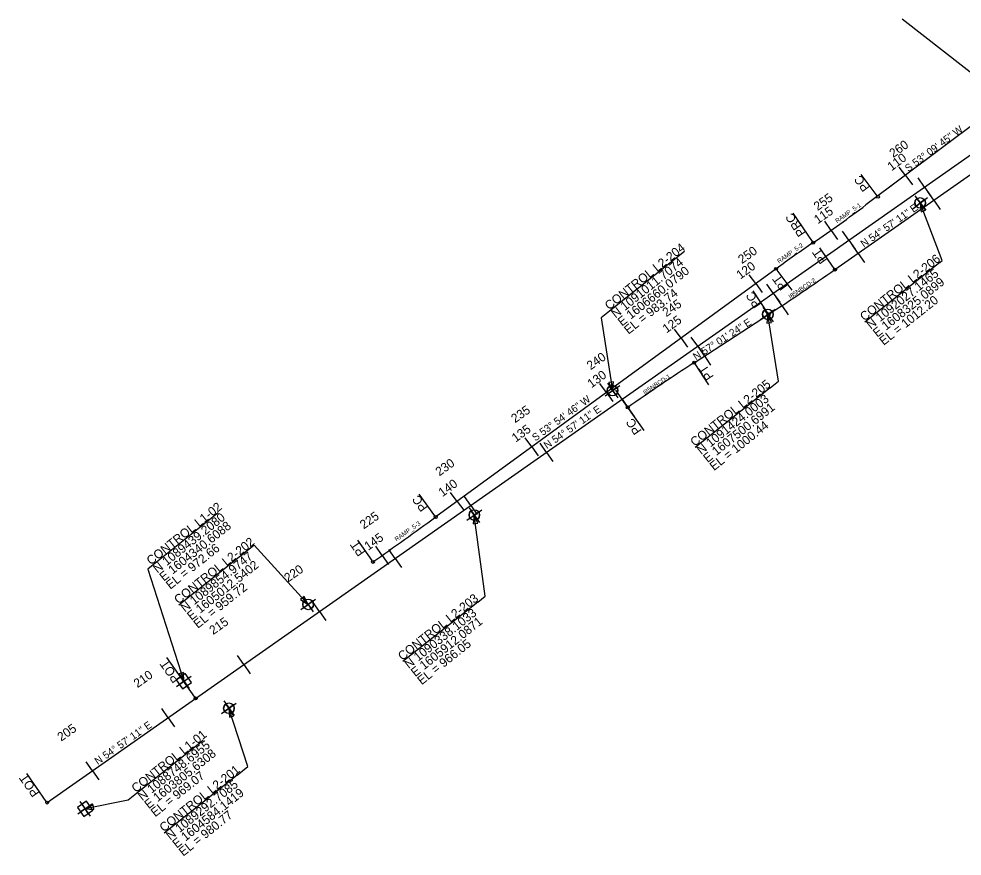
# Model space of a CAD drawing. Extents: x 1603447 to 1622636, y 1083818 to 1103958.
# Drawn here: x 1603447 to 1608552, y 1088493 to 1093023 of the extents above; entities that cross this region are included whole.
import ezdxf

# ---------------------------------------------------------------- set-up
doc = ezdxf.new("R2010")
doc.units = 0
for name, color, linetype in [('Level 1', 7, 'Continuous'), ('RD_HC_Points', 7, 'Continuous'), ('RD_HC_SUR_Bearing_TX400', 7, 'Continuous'), ('RD_HC_SUR_CL400', 7, 'Continuous'), ('RD_HC_SUR_PC_PT_400', 7, 'Continuous'), ('RD_HC_SUR_Tic400', 7, 'Continuous'), ('RD_HC_SUR_TX_Sta400', 7, 'Continuous'), ('RD_SHT_Misc1', 7, 'Continuous'), ('RD_TX_Misc1', 7, 'Continuous')]:
    doc.layers.add(name, color=color, linetype=linetype)

msp = doc.modelspace()

# ---------------------------------------------------------------- linework, layer by layer
at = {"layer": 'RD_HC_Points'}
for p, q in [((1607049.7, 1091764.6), (1606644.2, 1091442.1)), ((1608430.4, 1091704.3), (1608025.3, 1091382.1)), ((1607512.2, 1091026.1), (1607107.2, 1090703.9)), ((1604525.9, 1090349.5), (1604164.6, 1090062.1)), ((1604718.8, 1090172.8), (1604313.7, 1089850.6)), ((1605930.2, 1089867.2), (1605525.2, 1089545.1)), ((1604443.8, 1089117.6), (1604083, 1088830.6)), ((1604628.1, 1088930.9), (1604234.4, 1088617.7))]:
    msp.add_line(p, q, dxfattribs=at)
for points in [[(1608430.4, 1091704.3), (1608444.7, 1091715.7), (1608325.1, 1092027.1)], [(1606644.2, 1091442.1), (1606598.8, 1091405.9), (1606660.1, 1091011.7)], [(1607512.2, 1091026.1), (1607558.1, 1091062.6), (1607500.7, 1091424)], [(1605930.2, 1089867.2), (1605970.6, 1089899.4), (1605912.1, 1090338.1)], [(1604718.8, 1090172.8), (1604721.4, 1090174.9), (1605012.5, 1089855)], [(1604164.6, 1090062.1), (1604144.7, 1090046.2), (1604340.6, 1089439.2)], [(1604628.1, 1088930.9), (1604687, 1088977.7), (1604584.1, 1089292.7)], [(1604083, 1088830.6), (1604038.5, 1088795.2), (1603805.6, 1088748.7)]]:
    msp.add_lwpolyline(points, dxfattribs=at)
for points in [[(1608353.3, 1091988.3), (1608325.1, 1092027.1), (1608330.1, 1091979.4)], [(1607520.2, 1091380.2), (1607500.7, 1091424), (1607495.7, 1091376.3)], [(1606640.7, 1091055.6), (1606660.1, 1091011.7), (1606665.2, 1091059.4)], [(1605930.5, 1090293.8), (1605912.1, 1090338.1), (1605905.9, 1090290.5)], [(1604972.1, 1089880.9), (1605012.5, 1089855), (1604990.5, 1089897.6)], [(1604314.5, 1089479.5), (1604340.6, 1089439.2), (1604338.2, 1089487.1)], [(1604610.3, 1089252.5), (1604584.1, 1089292.7), (1604586.7, 1089244.8)], [(1603848.7, 1088770), (1603805.6, 1088748.7), (1603853.5, 1088745.6)]]:
    msp.add_lwpolyline(points, close=True, dxfattribs=at)
at = {"layer": 'RD_HC_SUR_CL400'}
for p, q in [((1608227.5, 1093023.1), (1609664.5, 1091901.4)), ((1608645.4, 1092476.2), (1608031.1, 1092016.1)), ((1604403.9, 1089345.9), (1608671.2, 1092339.1)), ((1607863.8, 1091666.5), (1608721.2, 1092267.8)), ((1607545.2, 1091670.4), (1605703, 1090327.7)), ((1607101.8, 1091162.7), (1607504.5, 1091424)), ((1603600.5, 1088782.3), (1604403.9, 1089345.9))]:
    msp.add_line(p, q, dxfattribs=at)
for centre, radius, start, end in [((1603234.8, 1098418.8), 8000, 304.32676, 306.83762), ((1612257.3, 1085205.5), 8000, 124.32676, 126.08708), ((1600972.9, 1101490.7), 12000, 302.97679, 305.04683), ((1613633.4, 1081096.1), 12000, 122.97679, 125.04683), ((1592155.7, 1108914.5), 23000, 305.04683, 306.08708)]:
    msp.add_arc(centre, radius, start, end, dxfattribs=at)
at = {"layer": 'RD_HC_SUR_PC_PT_400'}
for p, q in [((1608091.2, 1092066.4), (1608005, 1092181.5)), ((1607741.6, 1091818.8), (1607638.4, 1091971.6)), ((1607859.3, 1091673.1), (1607781.2, 1091784.3)), ((1607549.9, 1091664), (1607630, 1091554.2)), ((1607500.1, 1091430.7), (1607421.9, 1091551.3)), ((1607106.2, 1091156), (1607180.1, 1091042.1)), ((1606747.1, 1090913.7), (1606829.6, 1090796)), ((1605698.3, 1090334.2), (1605613.6, 1090450.4)), ((1605358.8, 1090091.4), (1605280.8, 1090202.6)), ((1604399.3, 1089352.4), (1604248.1, 1089567.9)), ((1603595.9, 1088788.9), (1603490.5, 1088939))]:
    msp.add_line(p, q, dxfattribs=at)
for centre in [(1608096, 1092060), (1607746, 1091812.1), (1607545.2, 1091670.4), (1607863.8, 1091666.5), (1607504.5, 1091424), (1607101.8, 1091162.7), (1606742.5, 1090920.3), (1605703, 1090327.7), (1605363.3, 1090084.8), (1604403.9, 1089345.9), (1603600.5, 1088782.3)]:
    msp.add_circle(centre, 8, dxfattribs=at)
at = {"layer": 'RD_HC_SUR_Tic400'}
for p, q in [((1608487.7, 1092353.2), (1608487.7, 1092353.2)), ((1608407.6, 1092293.2), (1608407.6, 1092293.2)), ((1608247.5, 1092173.4), (1608211.6, 1092221.4)), ((1608327.6, 1092233.3), (1608327.6, 1092233.3)), ((1608512.6, 1092227.8), (1608512.6, 1092227.8)), ((1608247.5, 1092173.4), (1608283.5, 1092125.4)), ((1608348.8, 1092113), (1608314.4, 1092162.1)), ((1608430.7, 1092170.4), (1608430.7, 1092170.4)), ((1608167.5, 1092113.5), (1608167.5, 1092113.5)), ((1608348.8, 1092113), (1608383.3, 1092063.8)), ((1608398.4, 1092041.4), (1608363.9, 1092090.6)), ((1608480.2, 1092098.9), (1608480.2, 1092098.9)), ((1608087.4, 1092053.6), (1608087.4, 1092053.6)), ((1608267, 1092055.5), (1608267, 1092055.5)), ((1608398.4, 1092041.4), (1608432.8, 1091992.3)), ((1608006.9, 1091994.2), (1608006.9, 1091994.2)), ((1608185.1, 1091998.1), (1608185.1, 1091998.1)), ((1607925.7, 1091935.9), (1607925.7, 1091935.9)), ((1608103.2, 1091940.7), (1608103.2, 1091940.7)), ((1608316.5, 1091984), (1608316.5, 1091984)), ((1607843.7, 1091878.7), (1607809.6, 1091928)), ((1608021.3, 1091883.3), (1608021.3, 1091883.3)), ((1608234.6, 1091926.6), (1608234.6, 1091926.6)), ((1607843.7, 1091878.7), (1607877.7, 1091829.3)), ((1607939.5, 1091825.8), (1607905, 1091874.9)), ((1608152.8, 1091869.2), (1608152.8, 1091869.2)), ((1607761, 1091822.3), (1607761, 1091822.3)), ((1607939.5, 1091825.8), (1607973.9, 1091776.7)), ((1607989, 1091754.3), (1607954.6, 1091803.4)), ((1608070.9, 1091811.7), (1608070.9, 1091811.7)), ((1607678.7, 1091765.6), (1607678.7, 1091765.6)), ((1607857.6, 1091768.4), (1607857.6, 1091768.4)), ((1607989, 1091754.3), (1608023.5, 1091705.2)), ((1607597, 1091707.9), (1607597, 1091707.9)), ((1607775.7, 1091711), (1607775.7, 1091711)), ((1607907.2, 1091696.9), (1607907.2, 1091696.9)), ((1607435.3, 1091590.3), (1607399.9, 1091638.8)), ((1607516.1, 1091649.2), (1607516.1, 1091649.2)), ((1607693.9, 1091653.6), (1607693.9, 1091653.6)), ((1607825.2, 1091639.5), (1607825.2, 1091639.5)), ((1607435.3, 1091590.3), (1607470.6, 1091541.8)), ((1607530.1, 1091538.7), (1607495.7, 1091587.8)), ((1607612, 1091596.1), (1607612, 1091596.1)), ((1607742.9, 1091582.8), (1607742.9, 1091582.8)), ((1607354.5, 1091531.4), (1607354.5, 1091531.4)), ((1607530.1, 1091538.7), (1607564.6, 1091489.6)), ((1607660.1, 1091526.7), (1607660.1, 1091526.7)), ((1607448.3, 1091481.3), (1607448.3, 1091481.3)), ((1607576.8, 1091471.3), (1607543.8, 1091521.4)), ((1607273.6, 1091472.5), (1607273.6, 1091472.5)), ((1607366.4, 1091423.9), (1607366.4, 1091423.9)), ((1607576.8, 1091471.3), (1607609.9, 1091421.2)), ((1607192.8, 1091413.6), (1607192.8, 1091413.6)), ((1607493.1, 1091416.6), (1607493.1, 1091416.6)), ((1607031.2, 1091295.8), (1606995.9, 1091344.3)), ((1607112, 1091354.7), (1607112, 1091354.7)), ((1607284.5, 1091366.4), (1607284.5, 1091366.4)), ((1607409.2, 1091362.2), (1607409.2, 1091362.2)), ((1607031.2, 1091295.8), (1607066.5, 1091247.3)), ((1607120.8, 1091251.6), (1607086.3, 1091300.7)), ((1607202.7, 1091309), (1607202.7, 1091309)), ((1607325.3, 1091307.8), (1607325.3, 1091307.8)), ((1606950.4, 1091236.9), (1606950.4, 1091236.9)), ((1607120.8, 1091251.6), (1607155.3, 1091202.5)), ((1607157.6, 1091198.9), (1607124.9, 1091249.3)), ((1607241.5, 1091253.3), (1607241.5, 1091253.3)), ((1606869.6, 1091178), (1606869.6, 1091178)), ((1607038.9, 1091194.2), (1607038.9, 1091194.2)), ((1607157.6, 1091198.9), (1607190.2, 1091148.6)), ((1606788.8, 1091119.1), (1606788.8, 1091119.1)), ((1606957.1, 1091136.7), (1606957.1, 1091136.7)), ((1607073.7, 1091144.4), (1607073.7, 1091144.4)), ((1606875.2, 1091079.3), (1606875.2, 1091079.3)), ((1606990.2, 1091089.4), (1606990.2, 1091089.4)), ((1606627.1, 1091001.3), (1606591.8, 1091049.8)), ((1606708, 1091060.2), (1606708, 1091060.2)), ((1606793.3, 1091021.9), (1606793.3, 1091021.9)), ((1606907.1, 1091033.7), (1606907.1, 1091033.7)), ((1606627.1, 1091001.3), (1606662.5, 1090952.8)), ((1606711.5, 1090964.5), (1606677, 1091013.6)), ((1606742.5, 1090920.3), (1606708, 1090969.4)), ((1606711.5, 1090964.5), (1606745.9, 1090915.3)), ((1606824.6, 1090977.3), (1606824.6, 1090977.3)), ((1606546.3, 1090942.4), (1606546.3, 1090942.4)), ((1606742.5, 1090920.3), (1606776.9, 1090871.1)), ((1606465.5, 1090883.5), (1606465.5, 1090883.5)), ((1606629.6, 1090907), (1606629.6, 1090907)), ((1606384.7, 1090824.6), (1606384.7, 1090824.6)), ((1606547.7, 1090849.6), (1606547.7, 1090849.6)), ((1606303.9, 1090765.7), (1606303.9, 1090765.7)), ((1606465.8, 1090792.2), (1606465.8, 1090792.2)), ((1606223.1, 1090706.8), (1606187.7, 1090755.3)), ((1606302.1, 1090677.3), (1606267.7, 1090726.5)), ((1606384, 1090734.8), (1606384, 1090734.8)), ((1606223.1, 1090706.8), (1606258.4, 1090658.3)), ((1606302.1, 1090677.3), (1606336.6, 1090628.2)), ((1606142.3, 1090647.9), (1606142.3, 1090647.9)), ((1606220.2, 1090619.9), (1606220.2, 1090619.9)), ((1606061.5, 1090589), (1606061.5, 1090589)), ((1606138.4, 1090562.5), (1606138.4, 1090562.5)), ((1605980.6, 1090530.1), (1605980.6, 1090530.1)), ((1606056.5, 1090505.1), (1606056.5, 1090505.1)), ((1605819, 1090412.3), (1605783.7, 1090460.7)), ((1605899.8, 1090471.2), (1605899.8, 1090471.2)), ((1605819, 1090412.3), (1605854.4, 1090363.8)), ((1605892.8, 1090390.2), (1605858.3, 1090439.3)), ((1605974.6, 1090447.6), (1605974.6, 1090447.6)), ((1605738.2, 1090353.4), (1605738.2, 1090353.4)), ((1605892.8, 1090390.2), (1605927.2, 1090341.1)), ((1605810.9, 1090332.8), (1605810.9, 1090332.8)), ((1605657.4, 1090294.5), (1605657.4, 1090294.5)), ((1605729, 1090275.4), (1605729, 1090275.4)), ((1605576.3, 1090236), (1605576.3, 1090236)), ((1605647.2, 1090217.9), (1605647.2, 1090217.9)), ((1605413.3, 1090120), (1605378.8, 1090169)), ((1605483.4, 1090103.1), (1605449, 1090152.2)), ((1605494.9, 1090177.8), (1605494.9, 1090177.8)), ((1605565.3, 1090160.5), (1605565.3, 1090160.5)), ((1605413.3, 1090120), (1605447.9, 1090071)), ((1605483.4, 1090103.1), (1605517.9, 1090054)), ((1605401.6, 1090045.7), (1605401.6, 1090045.7)), ((1605319.7, 1089988.2), (1605319.7, 1089988.2)), ((1605237.8, 1089930.8), (1605237.8, 1089930.8)), ((1605074.1, 1089816), (1605039.6, 1089865.1)), ((1605156, 1089873.4), (1605156, 1089873.4)), ((1605074.1, 1089816), (1605108.5, 1089766.8)), ((1604992.2, 1089758.5), (1604992.2, 1089758.5)), ((1604910.4, 1089701.1), (1604910.4, 1089701.1)), ((1604828.5, 1089643.7), (1604828.5, 1089643.7)), ((1604746.6, 1089586.3), (1604746.6, 1089586.3)), ((1604664.7, 1089528.8), (1604630.3, 1089578)), ((1604664.7, 1089528.8), (1604699.2, 1089479.7)), ((1604582.9, 1089471.4), (1604582.9, 1089471.4)), ((1604501, 1089414), (1604501, 1089414)), ((1604419.1, 1089356.6), (1604419.1, 1089356.6)), ((1604255.4, 1089241.7), (1604221, 1089290.8)), ((1604337.3, 1089299.1), (1604337.3, 1089299.1)), ((1604255.4, 1089241.7), (1604289.9, 1089192.6)), ((1604173.5, 1089184.3), (1604173.5, 1089184.3)), ((1604091.7, 1089126.9), (1604091.7, 1089126.9)), ((1604009.8, 1089069.4), (1604009.8, 1089069.4)), ((1603846.1, 1088954.6), (1603811.6, 1089003.7)), ((1603927.9, 1089012), (1603927.9, 1089012)), ((1603846.1, 1088954.6), (1603880.5, 1088905.5)), ((1603764.2, 1088897.2), (1603764.2, 1088897.2)), ((1603682.3, 1088839.8), (1603682.3, 1088839.8)), ((1603600.5, 1088782.3), (1603600.5, 1088782.3))]:
    msp.add_line(p, q, dxfattribs=at)
at = {"layer": 'RD_SHT_Misc1'}
for p, q in [((1608286.3, 1091997.6), (1608363.9, 1092056.7)), ((1608295.6, 1092066), (1608354.6, 1091988.3)), ((1608325.1, 1092027.1), (1608307.7, 1092050)), ((1608348, 1092044.5), (1608325.1, 1092027.1)), ((1608302.2, 1092009.7), (1608325.1, 1092027.1)), ((1608325.1, 1092027.1), (1608342.5, 1092004.3)), ((1607460.8, 1091396), (1607540.6, 1091452)), ((1607472.7, 1091463.9), (1607528.7, 1091384.1)), ((1607477.2, 1091407.5), (1607500.7, 1091424)), ((1607500.7, 1091424), (1607484.2, 1091447.5)), ((1607524.2, 1091440.5), (1607500.7, 1091424)), ((1607500.7, 1091424), (1607517.2, 1091400.5)), ((1606620.2, 1090983.7), (1606700, 1091039.7)), ((1606632.1, 1091051.6), (1606688.1, 1090971.8)), ((1606660.1, 1091011.7), (1606643.6, 1091035.2)), ((1606683.6, 1091028.2), (1606660.1, 1091011.7)), ((1606636.5, 1090995.2), (1606660.1, 1091011.7)), ((1606660.1, 1091011.7), (1606676.6, 1090988.2)), ((1605872.2, 1090310.1), (1605952, 1090366.1)), ((1605884.1, 1090378), (1605940.1, 1090298.2)), ((1605912.1, 1090338.1), (1605895.6, 1090361.6)), ((1605935.6, 1090354.6), (1605912.1, 1090338.1)), ((1605888.6, 1090321.6), (1605912.1, 1090338.1)), ((1605912.1, 1090338.1), (1605928.6, 1090314.6)), ((1604984.5, 1089894.9), (1605040.5, 1089815.1)), ((1604972.6, 1089827), (1605052.4, 1089883)), ((1604989, 1089838.5), (1605012.5, 1089855)), ((1605012.5, 1089855), (1604996, 1089878.5)), ((1605036.1, 1089871.5), (1605012.5, 1089855)), ((1605012.5, 1089855), (1605029.1, 1089831.4)), ((1604300.7, 1089411.2), (1604380.5, 1089467.2)), ((1604312.6, 1089479.1), (1604368.6, 1089399.3)), ((1604340.6, 1089439.2), (1604316.1, 1089422)), ((1604323.4, 1089463.8), (1604340.6, 1089439.2)), ((1604340.6, 1089439.2), (1604365.2, 1089456.4)), ((1604357.8, 1089414.7), (1604340.6, 1089439.2)), ((1604556.1, 1089332.6), (1604612.1, 1089252.8)), ((1604544.2, 1089264.7), (1604624, 1089320.7)), ((1604560.6, 1089276.2), (1604584.1, 1089292.7)), ((1604584.1, 1089292.7), (1604567.6, 1089316.2)), ((1604607.7, 1089309.2), (1604584.1, 1089292.7)), ((1604584.1, 1089292.7), (1604600.7, 1089269.2)), ((1603765.7, 1088720.7), (1603845.5, 1088776.7)), ((1603777.6, 1088788.6), (1603833.6, 1088708.8)), ((1603788.4, 1088773.3), (1603805.6, 1088748.7)), ((1603805.6, 1088748.7), (1603781.1, 1088731.5)), ((1603805.6, 1088748.7), (1603830.2, 1088765.9)), ((1603822.9, 1088724.1), (1603805.6, 1088748.7))]:
    msp.add_line(p, q, dxfattribs=at)
for points in [[(1604333.3, 1089397.4), (1604382.4, 1089431.9), (1604347.9, 1089481), (1604298.8, 1089446.5)], [(1603798.3, 1088706.9), (1603847.4, 1088741.4), (1603813, 1088790.5), (1603763.8, 1088756)]]:
    msp.add_lwpolyline(points, close=True, dxfattribs=at)
for points in [[(1604365.2, 1089456.4), (1604347.9, 1089481), (1604323.4, 1089463.8)], [(1604316.1, 1089422), (1604333.3, 1089397.4)], [(1604333.3, 1089397.4), (1604357.8, 1089414.7)], [(1603830.2, 1088765.9), (1603813, 1088790.5), (1603788.4, 1088773.3)], [(1603781.1, 1088731.5), (1603798.3, 1088706.9)], [(1603798.3, 1088706.9), (1603822.9, 1088724.1)]]:
    msp.add_lwpolyline(points, dxfattribs=at)
for centre in [(1608325.1, 1092027.1), (1607500.7, 1091424), (1606660.1, 1091011.7), (1605912.1, 1090338.1), (1605012.5, 1089855), (1604584.1, 1089292.7)]:
    msp.add_circle(centre, 28.8, dxfattribs=at)
for centre, start, end in [((1608325.1, 1092027.1), 127.2464, 217.2464), ((1608325.1, 1092027.1), 307.2464, 37.2464), ((1607500.7, 1091424), 125.0534, 215.0534), ((1607500.7, 1091424), 305.0534, 35.0534), ((1606660.1, 1091011.7), 125.0534, 215.0534), ((1606660.1, 1091011.7), 305.0534, 35.0534), ((1605912.1, 1090338.1), 125.0534, 215.0534), ((1605912.1, 1090338.1), 305.0534, 35.0534), ((1605012.5, 1089855), 125.0534, 215.0534), ((1605012.5, 1089855), 305.0534, 35.0534), ((1604584.1, 1089292.7), 125.0534, 215.0534), ((1604584.1, 1089292.7), 305.0534, 35.0534)]:
    msp.add_arc(centre, 28.8, start, end, dxfattribs=at)

# ---------------------------------------------------------------- texts
at = {"layer": 'Level 1'}
for s, rotation, p in [('255', 35.0468, (1607769.8, 1091982.8)), ('115', 34.5898, (1607770.9, 1091911.3)), ('245', 35.0468, (1606951.1, 1091408.6)), ('125', 36.0871, (1606952.6, 1091320.6)), ('235', 35.0468, (1606132.4, 1090834.4)), ('135', 36.0871, (1606136.3, 1090730)), ('225', 35.0468, (1605313.7, 1090260.1)), ('145', 35.1991, (1605337.9, 1090144.6)), ('215', 35.0468, (1604498.8, 1089688.5)), ('205', 35.0468, (1603676.4, 1089111.6))]:
    msp.add_text(s, height=48, rotation=rotation, dxfattribs=at).set_placement(p)
at = {"layer": 'RD_HC_Points'}
for s, p in [('CONTROL L2-204', (1606641.7, 1091445.2)), ('CONTROL L2-206', (1608022.9, 1091385.2)), ('N 1091011.7074', (1606676.6, 1091401.4)), ('E 1606660.0790', (1606711.4, 1091357.6)), ('N 1092027.1465', (1608057.7, 1091341.4)), ('E 1608325.0899', (1608092.6, 1091297.6)), ('EL = 983.74', (1606746.3, 1091313.7)), ('EL = 1012.20', (1608127.4, 1091253.8)), ('CONTROL L2-205', (1607104.7, 1090707)), ('N 1091424.0003', (1607139.6, 1090663.2)), ('E 1607500.6991', (1607174.4, 1090619.4)), ('EL = 1000.44', (1607209.3, 1090575.6)), ('CONTROL L1-02', (1604162.1, 1090065.2)), ('N 1089439.2080', (1604197, 1090021.4)), ('E 1604340.6088', (1604231.8, 1089977.6)), ('CONTROL L2-202', (1604311.2, 1089853.7)), ('EL = 972.66', (1604266.7, 1089933.7)), ('N 1089854.9747', (1604346.1, 1089809.9)), ('E 1605012.5402', (1604381, 1089766.1)), ('EL = 959.72', (1604415.8, 1089722.2)), ('CONTROL L2-203', (1605522.7, 1089548.2)), ('N 1090338.1033', (1605557.5, 1089504.4)), ('E 1605912.0871', (1605592.4, 1089460.5)), ('EL = 966.05', (1605627.3, 1089416.7)), ('CONTROL L1-01', (1604080.5, 1088833.7)), ('N 1088748.6955', (1604115.3, 1088789.9)), ('E 1603805.6308', (1604150.2, 1088746)), ('CONTROL L2-201', (1604231.9, 1088620.8)), ('EL = 969.07', (1604185, 1088702.2)), ('N 1089292.7085', (1604266.8, 1088577)), ('E 1604584.1419', (1604301.6, 1088533.1)), ('EL = 980.77', (1604336.5, 1088489.3))]:
    msp.add_text(s, height=48, rotation=38.4995, dxfattribs=at).set_placement(p)
at = {"layer": 'RD_HC_SUR_Bearing_TX400'}
for s, rotation, p in [('S 53%%d 09\' 45" W', 36.8151, (1608260.5, 1092192.7)), ('N 54%%d 57\' 11" E', 35.0468, (1608019.9, 1091784.8)), ('N 57%%d 01\' 24" E', 32.9768, (1607111.7, 1091174.2)), ('S 53%%d 54\' 46" W', 36.0871, (1606242.3, 1090735.9)), ('N 54%%d 57\' 11" E', 35.0468, (1606305.3, 1090694.1)), ('N 54%%d 57\' 11" E', 35.0468, (1603874.2, 1088985.1))]:
    msp.add_text(s, height=40, rotation=rotation, dxfattribs=at).set_placement(p)
at = {"layer": 'RD_HC_SUR_PC_PT_400'}
for s, rotation, p in [('PC', 126.8151, (1608055.4, 1092110.8)), ('PRC', 124.0352, (1607708, 1091864.9)), ('PT', 125.0468, (1607824.9, 1091718.6)), ('PT', 126.0871, (1607609.6, 1091576)), ('PC', 122.9768, (1607467.4, 1091477.5)), ('PT', 122.9768, (1607209.7, 1091087.2)), ('PC', 125.0468, (1606819.6, 1090794.3)), ('PC', 126.0871, (1605663.1, 1090379.1)), ('PT', 125.0468, (1605324.4, 1090136.9)), ('POT', 125.0468, (1604322.5, 1089451.2)), ('POT', 125.0468, (1603561.5, 1088834.4))]:
    msp.add_text(s, height=48, rotation=rotation, dxfattribs=at).set_placement(p)
at = {"layer": 'RD_HC_SUR_TX_Sta400'}
for s, rotation, p in [('260', 35.0468, (1608178.9, 1092269.8)), ('110', 36.8151, (1608170, 1092197.7)), ('250', 35.0468, (1607360.2, 1091695.6)), ('120', 36.0871, (1607351.8, 1091611.9)), ('240', 35.0468, (1606541.5, 1091121.3)), ('130', 36.0871, (1606545.7, 1091023.3)), ('230', 35.0468, (1605722.8, 1090547.1)), ('140', 36.0871, (1605739.6, 1090434.7)), ('220', 35.0468, (1604904.2, 1089972.8)), ('210', 35.0468, (1604089.3, 1089401.2))]:
    msp.add_text(s, height=48, rotation=rotation, dxfattribs=at).set_placement(p)
at = {"layer": 'RD_TX_Misc1'}
for s, rotation, p in [('RAMP_5-1', 35.2913, (1607875.5, 1091916.7)), ('RAMP_5-2', 35.2913, (1607561.6, 1091698.5)), ('I85NBCD-2', 34.1616, (1607622.3, 1091507.2)), ('I85NBCD-1', 33.804, (1606834.9, 1090988.9)), ('RAMP_5-3', 34.9881, (1605491.1, 1090194.9))]:
    msp.add_text(s, height=24, rotation=rotation, dxfattribs=at).set_placement(p)

doc.saveas('drawing.dxf')
